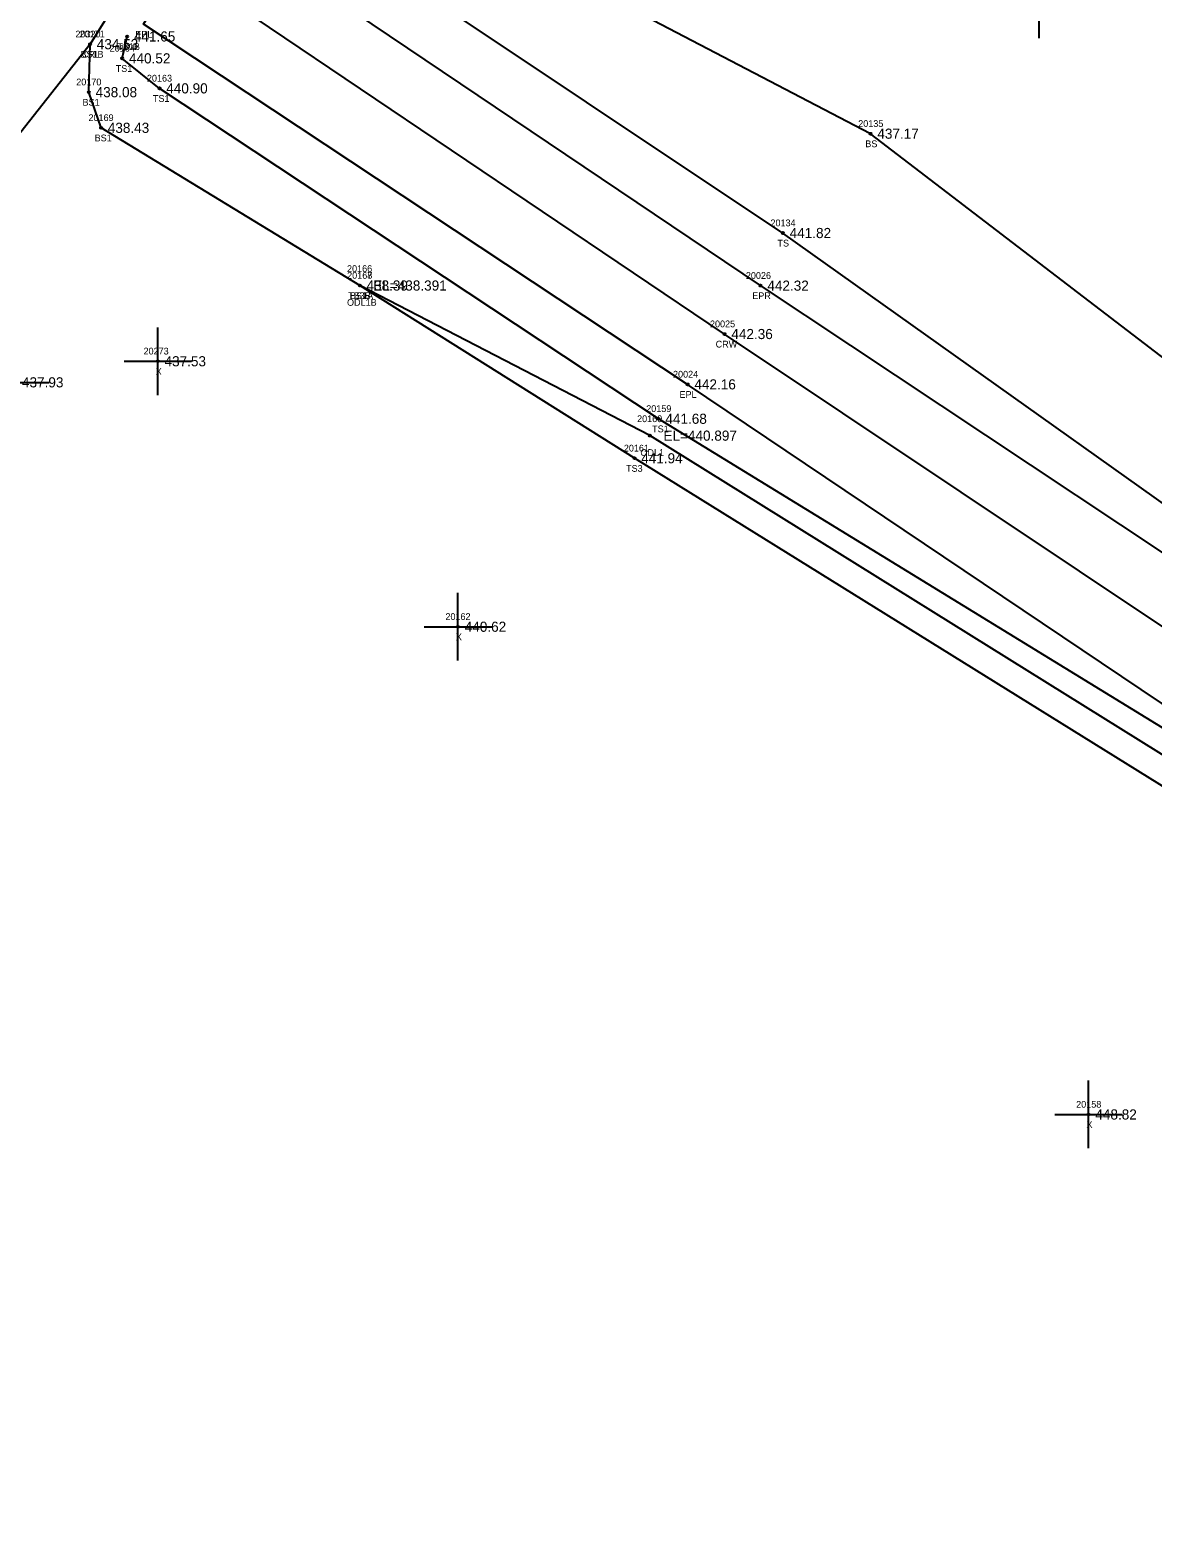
# Model space of a CAD drawing. Extents: x 1797709 to 1799052, y 896018 to 896955.
# Drawn here: x 1798378.7 to 1798544.9, y 896239.9 to 896463 of the extents above; entities that cross this region are included whole.
import ezdxf

# ---------------------------------------------------------------- set-up
doc = ezdxf.new("R2010")
doc.units = 0
for name, color, linetype in [('RD_DTM_BkLn1', 7, 'Continuous'), ('RD_DTM_BkLn2', 7, 'Continuous'), ('RD_DTM_BkLn_txCode', 7, 'Continuous'), ('RD_EX_H2O', 7, 'Continuous'), ('RD_EX_H2O_txCode', 7, 'Continuous'), ('RD_EX_Misc', 7, 'Continuous'), ('RD_EX_Misc_txCode', 7, 'Continuous'), ('RD_EX_Road', 7, 'Continuous'), ('RD_EX_Road_txCode', 7, 'Continuous'), ('RD_EX_TX_H2O_ELEV', 7, 'Continuous'), ('RD_EX_TX_Misc_ELEV', 7, 'Continuous'), ('RD_EX_TX_Road_ELEV', 7, 'Continuous'), ('RD_HC_Survey_ELEV', 7, 'Continuous'), ('RD_HC_Survey_txCode', 7, 'Continuous'), ('RD_SMD_Locator', 7, 'Continuous')]:
    doc.layers.add(name, color=color, linetype=linetype)

msp = doc.modelspace()

# ---------------------------------------------------------------- linework, layer by layer
at = {"layer": 'RD_DTM_BkLn1'}
msp.add_lwpolyline([(1799011.08, 896069.91), (1798925.85, 896126.62), (1798837.59, 896184.3), (1798748.15, 896241.48), (1798659.28, 896299.6), (1798569.04, 896359.56), (1798481.49, 896418.06), (1798400.67, 896472.53)], dxfattribs=at)
at = {"layer": 'RD_DTM_BkLn2'}
for points in [[(1798779.67, 896245.03), (1798759.32, 896261.95), (1798678.07, 896324.5), (1798585.68, 896384.49), (1798503.1, 896447.71), (1798419.26, 896491.43), (1798406.44, 896491.18)], [(1799018.13, 896081.6), (1798933.54, 896137.5), (1798843.36, 896196.36), (1798754.6, 896254.77), (1798666.48, 896312.08), (1798576.97, 896371.21), (1798490.12, 896433.01), (1798431.99, 896471.79), (1798411.1, 896485.73), (1798407.22, 896483.62)], [(1798553.27, 896351.26), (1798553.7, 896355.25), (1798471.73, 896405.52), (1798397.85, 896454.42), (1798392.33, 896458.86), (1798393.06, 896462.1)], [(1798427.49, 896425.24), (1798389.2, 896448.58), (1798387.4, 896453.86), (1798387.57, 896460.96)], [(1798553.27, 896351.26), (1798549.15, 896349.36), (1798468.15, 896399.67), (1798427.49, 896425.24)]]:
    msp.add_lwpolyline(points, dxfattribs=at)
at = {"layer": 'RD_EX_H2O'}
for points in [[(1798443.56, 896510.19), (1798406.44, 896491.18), (1798387.57, 896460.96), (1798358.05, 896423.51), (1798298.17, 896368.97), (1798249.86, 896318.72)], [(1798551.41, 896352.62), (1798470.44, 896403.02), (1798427.49, 896425.24)]]:
    msp.add_lwpolyline(points, dxfattribs=at)
at = {"layer": 'RD_EX_Misc'}
for p, q in [((1798528.03, 896461.86), (1798528.03, 896471.86)), ((1798397.6, 896409.03), (1798397.6, 896419.03)), ((1798392.6, 896414.03), (1798402.6, 896414.03)), ((1798371.5, 896410.91), (1798381.5, 896410.91)), ((1798442.03, 896369.74), (1798442.03, 896379.74)), ((1798437.03, 896374.74), (1798447.03, 896374.74)), ((1798535.37, 896297.56), (1798535.37, 896307.56)), ((1798530.37, 896302.56), (1798540.37, 896302.56))]:
    msp.add_line(p, q, dxfattribs=at)
at = {"layer": 'RD_EX_Road'}
for points in [[(1799016.83, 896078.37), (1798931.94, 896134.3), (1798843.73, 896191.67), (1798753.3, 896249.87), (1798664.51, 896307.9), (1798573.47, 896367.69), (1798486.82, 896425.22), (1798405.79, 896479.79), (1798400.67, 896472.53)], [(1799005.77, 896063.27), (1798987.67, 896075.09), (1798974.89, 896083.47), (1798920.67, 896119.42), (1798834.47, 896175.11), (1798832.16, 896176.64), (1798822.63, 896182.83), (1798742.86, 896234.39), (1798653.4, 896292.37), (1798563.64, 896351.71), (1798476.02, 896410.61), (1798395.49, 896463.92), (1798400.67, 896472.53)]]:
    msp.add_lwpolyline(points, dxfattribs=at)
at = {"layer": 'RD_SMD_Locator'}
for centre in [(1798393.06, 896462.1), (1798387.57, 896460.96), (1798387.57, 896460.96), (1798392.33, 896458.86), (1798387.4, 896453.86), (1798397.85, 896454.42), (1798389.2, 896448.58), (1798503.1, 896447.71), (1798490.12, 896433.01), (1798427.49, 896425.24), (1798427.49, 896425.24), (1798427.49, 896425.24), (1798486.82, 896425.22), (1798481.49, 896418.06), (1798397.6, 896414.03), (1798476.02, 896410.61), (1798471.73, 896405.52), (1798470.44, 896403.02), (1798468.15, 896399.67), (1798442.03, 896374.74), (1798535.37, 896302.56)]:
    msp.add_circle(centre, 0.15, dxfattribs=at)

# ---------------------------------------------------------------- texts
at = {"layer": 'RD_DTM_BkLn_txCode'}
for s, p in [('20171', (1798386.02, 896461.96)), ('BS1B', (1798386.15, 896458.96)), ('20164', (1798390.47, 896459.86)), ('TS1B', (1798391.62, 896460.1)), ('TS1', (1798391.37, 896456.86)), ('20170', (1798385.53, 896454.86)), ('20163', (1798395.99, 896455.42)), ('BS1', (1798386.46, 896451.86)), ('TS1', (1798396.88, 896452.42)), ('20169', (1798387.34, 896449.58)), ('20135', (1798501.27, 896448.71)), ('BS1', (1798388.25, 896446.58)), ('BS', (1798502.32, 896445.71)), ('20134', (1798488.28, 896434.01)), ('TS', (1798489.32, 896431.01)), ('20167', (1798425.63, 896426.24)), ('20168', (1798425.63, 896426.24)), ('TS3B', (1798425.77, 896423.24)), ('BS1A', (1798426.06, 896423.24)), ('20159', (1798469.89, 896406.52)), ('TS1', (1798470.77, 896403.52)), ('20161', (1798466.58, 896400.67)), ('TS3', (1798466.91, 896397.67))]:
    msp.add_text(s, height=1, dxfattribs=at).set_placement(p)
at = {"layer": 'RD_EX_H2O_txCode'}
for s, p in [('20320', (1798385.41, 896461.96)), ('CRL', (1798386.34, 896458.96)), ('20166', (1798425.61, 896427.24)), ('ODL1B', (1798425.61, 896422.24)), ('20160', (1798468.54, 896405.02)), ('ODL1', (1798469.03, 896400.02))]:
    msp.add_text(s, height=1, dxfattribs=at).set_placement(p)
at = {"layer": 'RD_EX_Misc_txCode'}
for s, p in [('20273', (1798395.49, 896415.03)), ('X', (1798397.29, 896412.03)), ('20162', (1798440.17, 896375.74)), ('X', (1798441.71, 896372.74)), ('20158', (1798533.53, 896303.56)), ('X', (1798535.05, 896300.56))]:
    msp.add_text(s, height=1, dxfattribs=at).set_placement(p)
at = {"layer": 'RD_EX_Road_txCode'}
for s, p in [('EPL', (1798394.28, 896461.92)), ('20026', (1798484.64, 896426.22)), ('EPR', (1798485.59, 896423.22)), ('20024', (1798473.86, 896411.61)), ('EPL', (1798474.82, 896408.61))]:
    msp.add_text(s, height=1, dxfattribs=at).set_placement(p)
at = {"layer": 'RD_EX_TX_H2O_ELEV'}
for s, p in [('434.53', (1798388.57, 896460.21)), ('EL=438.391', (1798429.49, 896424.49)), ('EL=440.897', (1798472.44, 896402.27))]:
    msp.add_text(s, height=1.5, dxfattribs=at).set_placement(p)
at = {"layer": 'RD_EX_TX_Misc_ELEV'}
for s, p in [('441.65', (1798394.06, 896461.35)), ('434.53', (1798388.57, 896460.21)), ('440.52', (1798393.33, 896458.11)), ('440.90', (1798398.85, 896453.67)), ('438.08', (1798388.4, 896453.11)), ('438.43', (1798390.2, 896447.83)), ('437.17', (1798504.1, 896446.96)), ('441.82', (1798491.12, 896432.26)), ('438.39', (1798428.49, 896424.49)), ('438.39', (1798428.49, 896424.49)), ('437.53', (1798398.6, 896413.28)), ('437.93', (1798377.5, 896410.16)), ('441.68', (1798472.73, 896404.77)), ('441.94', (1798469.15, 896398.92)), ('440.62', (1798443.03, 896373.99)), ('448.82', (1798536.37, 896301.81))]:
    msp.add_text(s, height=1.5, dxfattribs=at).set_placement(p)
at = {"layer": 'RD_EX_TX_Road_ELEV'}
for s, p in [('442.32', (1798487.82, 896424.47)), ('442.16', (1798477.02, 896409.86))]:
    msp.add_text(s, height=1.5, dxfattribs=at).set_placement(p)
at = {"layer": 'RD_HC_Survey_ELEV'}
msp.add_text('442.36', height=1.5, dxfattribs=at).set_placement((1798482.49, 896417.31))
at = {"layer": 'RD_HC_Survey_txCode'}
for s, p in [('20025', (1798479.33, 896419.06)), ('CRW', (1798480.17, 896416.06))]:
    msp.add_text(s, height=1, dxfattribs=at).set_placement(p)

doc.saveas('drawing.dxf')
